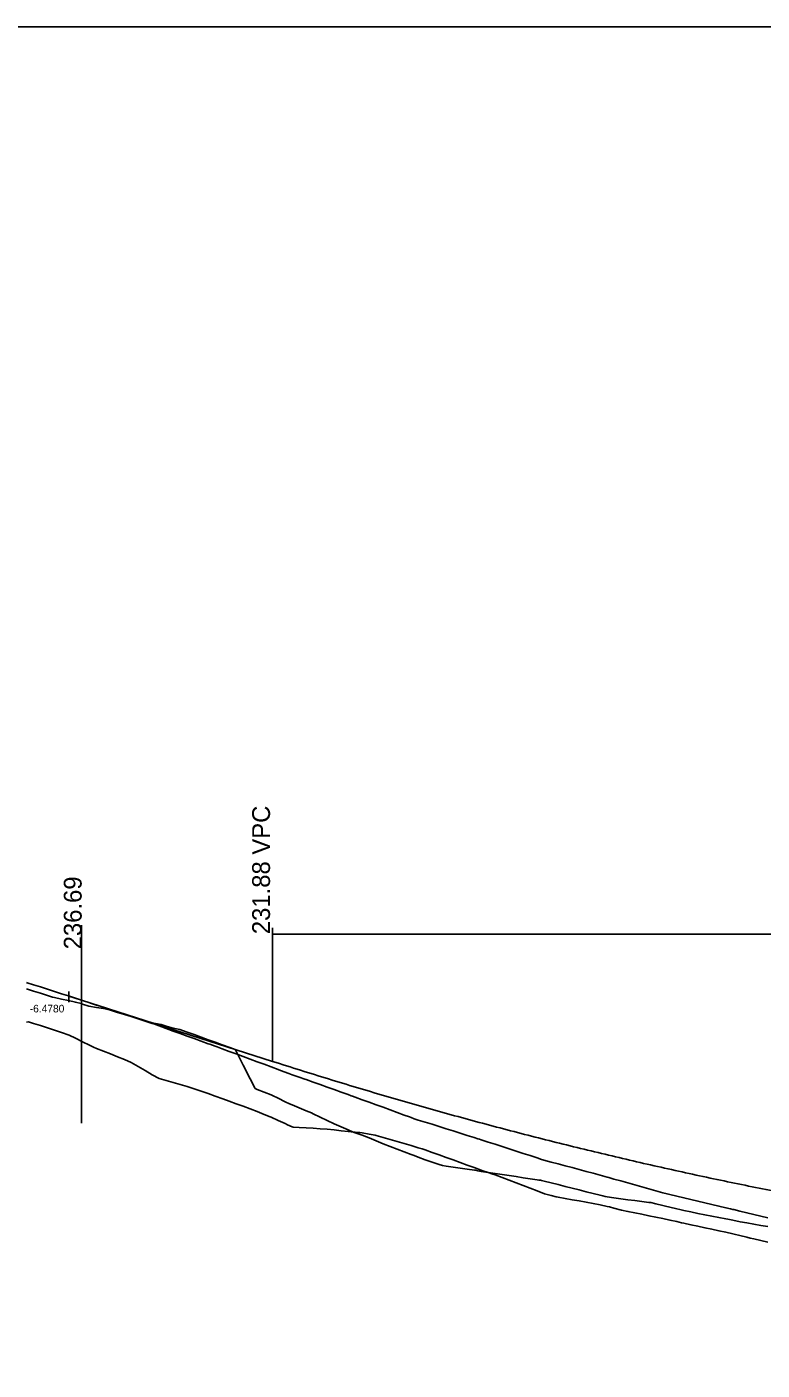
# Model space of a CAD drawing. Extents: x 2224795 to 2228395, y 930927 to 933127.
# Drawn here: x 2225784 to 2226072, y 932027 to 932554 of the extents above; entities that cross this region are included whole.
import ezdxf

# ---------------------------------------------------------------- set-up
doc = ezdxf.new("R2010")
doc.units = 0
for name, color, linetype in [('BR_EXIST_GROUND_LT', 7, 'Continuous'), ('BR_EXIST_GROUND_RT', 7, 'Continuous'), ('BR_USER NOTES', 7, 'Continuous'), ('RD_DDB_Profile_EX', 7, 'Continuous'), ('RD_DDB_Profile_Lbl', 7, 'Continuous'), ('RD_DDB_Profile_PR', 7, 'Continuous'), ('RD_DDB_StripGrade', 7, 'Continuous'), ('RD_DDB_VCLbl', 7, 'Continuous'), ('RD_SHT_ShtClip', 7, 'Continuous')]:
    doc.layers.add(name, color=color, linetype=linetype)

msp = doc.modelspace()

# ---------------------------------------------------------------- linework, layer by layer
at = {"layer": 'BR_EXIST_GROUND_LT'}
msp.add_lwpolyline([(2225783.36, 932163.35), (2225784.22, 932163.44), (2225786.11, 932162.85), (2225788.86, 932161.98), (2225791.6, 932161.1), (2225794.35, 932160.19), (2225797.1, 932159.27), (2225800.1, 932158.24), (2225802.6, 932157.01), (2225805.35, 932155.65), (2225808.09, 932154.26), (2225809.67, 932153.45), (2225810.84, 932153), (2225813.59, 932151.94), (2225816.34, 932150.85), (2225819.09, 932149.73), (2225821.84, 932148.6), (2225824.58, 932147.42), (2225827.33, 932145.87), (2225830.08, 932144.29), (2225832.83, 932142.69), (2225835.58, 932141.15), (2225838.33, 932140.41), (2225841.07, 932139.63), (2225843.82, 932138.83), (2225846.57, 932138.01), (2225849.32, 932137.16), (2225852.07, 932136.28), (2225854.81, 932135.3), (2225857.56, 932134.29), (2225860.57, 932133.16), (2225863.06, 932132.29), (2225865.81, 932131.3), (2225868.56, 932130.29), (2225871.3, 932129.25), (2225874.05, 932128.18), (2225876.8, 932127.09), (2225879.15, 932126.14), (2225879.55, 932125.96), (2225882.3, 932124.73), (2225885.05, 932123.46), (2225885.91, 932123.06), (2225887.79, 932122.24), (2225888.15, 932122.07), (2225890.54, 932121.97), (2225893.29, 932121.82), (2225896.04, 932121.65), (2225898.79, 932121.45), (2225901.54, 932121.23), (2225904.28, 932120.98), (2225907.03, 932120.7), (2225909.78, 932120.39), (2225911.98, 932120.13), (2225912.53, 932120.09), (2225913.43, 932120.01), (2225914.33, 932119.94), (2225915.28, 932119.79), (2225918.03, 932119.36), (2225920.41, 932118.97), (2225920.77, 932118.86), (2225923.52, 932118.07), (2225926.27, 932117.26), (2225929.02, 932116.46), (2225931.77, 932115.64), (2225934.51, 932114.83), (2225937.26, 932114), (2225938.86, 932113.51), (2225940.01, 932113.11), (2225942.76, 932112.14), (2225945.51, 932111.16), (2225948.26, 932110.18), (2225951, 932109.19), (2225953.75, 932108.19), (2225956.5, 932107.19), (2225959.25, 932106.18), (2225962, 932105.16), (2225962.34, 932105.04), (2225964.75, 932104.26), (2225966.26, 932103.76), (2225967.49, 932103.3), (2225970.24, 932102.27), (2225972.99, 932101.24), (2225975.74, 932100.19), (2225978.49, 932099.14), (2225981.24, 932098.08), (2225983.98, 932097.02), (2225986.92, 932095.87), (2225989.48, 932095.23), (2225991.55, 932094.71), (2225992.23, 932094.59), (2225994.98, 932094.09), (2225997.73, 932093.59), (2226000.47, 932093.08), (2226003.22, 932092.56), (2226005.97, 932092.04), (2226008.72, 932091.51), (2226011.47, 932090.98), (2226012.4, 932090.8), (2226014.21, 932090.3), (2226017.15, 932089.5), (2226019.71, 932088.99), (2226022.46, 932088.43), (2226025.21, 932087.87), (2226027.96, 932087.31), (2226030.7, 932086.74), (2226033.45, 932086.17), (2226036.2, 932085.59), (2226038.95, 932084.96), (2226040.74, 932084.54), (2226041.7, 932084.34), (2226044.45, 932083.76), (2226047.19, 932083.17), (2226049.94, 932082.58), (2226052.69, 932081.98), (2226055.44, 932081.38), (2226058.19, 932080.77), (2226060.94, 932080.16), (2226061.39, 932080.06), (2226063.68, 932079.5), (2226066.43, 932078.82), (2226067.77, 932078.49), (2226069.18, 932078.17), (2226071.93, 932077.54), (2226074.68, 932076.9)], dxfattribs=at)
at = {"layer": 'BR_EXIST_GROUND_RT'}
msp.add_lwpolyline([(2225783.36, 932176.39), (2225786.11, 932175.53), (2225788.86, 932174.68), (2225791.6, 932173.82), (2225793.61, 932173.21), (2225794.35, 932173.04), (2225797.1, 932172.41), (2225799.85, 932171.78), (2225802.6, 932171.14), (2225804.82, 932170.63), (2225805.35, 932170.45), (2225807.86, 932169.61), (2225810.84, 932169.14), (2225813.59, 932168.7), (2225814.29, 932168.59), (2225816.34, 932167.98), (2225819.09, 932167.16), (2225821.84, 932166.33), (2225824.58, 932165.51), (2225827.33, 932164.69), (2225830.08, 932163.87), (2225832.38, 932163.18), (2225832.83, 932163.09), (2225835.58, 932162.51), (2225836.32, 932162.35), (2225838.33, 932161.79), (2225841.07, 932161.02), (2225841.7, 932160.84), (2225843.59, 932160.5), (2225846.57, 932159.42), (2225849.32, 932158.42), (2225852.07, 932157.42), (2225854.81, 932156.43), (2225857.56, 932155.43), (2225860.31, 932154.43), (2225863.34, 932153.33), (2225865.41, 932152.64), (2225865.81, 932151.87), (2225868.56, 932146.47), (2225871.3, 932141.08), (2225873.25, 932137.27), (2225874.05, 932136.94), (2225876.8, 932135.83), (2225879.55, 932134.75), (2225880.07, 932134.54), (2225882.3, 932133.43), (2225885.05, 932132.07), (2225886.67, 932131.28), (2225887.79, 932130.8), (2225890.54, 932129.64), (2225893.29, 932128.5), (2225895.36, 932127.66), (2225896.04, 932127.33), (2225898.79, 932126.01), (2225901.54, 932124.72), (2225904.28, 932123.45), (2225907.03, 932122.2), (2225909.78, 932120.98), (2225911.48, 932120.24), (2225912.53, 932119.86), (2225915.28, 932118.9), (2225917.02, 932118.31), (2225918.03, 932117.88), (2225920.77, 932116.71), (2225923.52, 932115.58), (2225926.27, 932114.47), (2225929.02, 932113.39), (2225931.77, 932112.33), (2225934.51, 932111.3), (2225935.66, 932110.9), (2225937.26, 932110.3), (2225940.01, 932109.31), (2225942.76, 932108.35), (2225945.51, 932107.41), (2225946.79, 932106.99), (2225948.26, 932106.78), (2225951, 932106.38), (2225953.75, 932105.99), (2225956.5, 932105.6), (2225959.44, 932105.18), (2225959.87, 932105.24), (2225960.73, 932104.88), (2225962, 932104.69), (2225964.75, 932104.28), (2225967.49, 932103.87), (2225970.24, 932103.46), (2225972.99, 932103.05), (2225975.74, 932102.64), (2225978.49, 932102.23), (2225981.24, 932101.83), (2225983.98, 932101.42), (2225984.67, 932101.32), (2225985.37, 932101.22), (2225985.69, 932101.19), (2225986.73, 932100.92), (2225989.48, 932100.22), (2225992.23, 932099.52), (2225994.98, 932098.83), (2225997.73, 932098.13), (2226000.47, 932097.44), (2226003.22, 932096.74), (2226005.97, 932096.05), (2226008.72, 932095.35), (2226009.76, 932095.09), (2226010.71, 932094.85), (2226011.47, 932094.74), (2226014.21, 932094.34), (2226016.96, 932093.95), (2226019.71, 932093.58), (2226022.46, 932093.23), (2226025.21, 932092.88), (2226027.96, 932092.55), (2226028.69, 932092.46), (2226030.7, 932091.94), (2226033.45, 932091.25), (2226034.44, 932091.02), (2226036.2, 932090.6), (2226038.95, 932089.95), (2226040.08, 932089.69), (2226041.7, 932089.35), (2226044.45, 932088.78), (2226047.19, 932088.22), (2226049.94, 932087.66), (2226052.69, 932087.12), (2226055.44, 932086.59), (2226058.19, 932086.06), (2226058.91, 932085.93), (2226060.94, 932085.5), (2226063.77, 932084.92), (2226066.43, 932084.44), (2226069.18, 932083.95), (2226071.93, 932083.47), (2226074.68, 932083)], dxfattribs=at)
at = {"layer": 'BR_USER NOTES'}
for p, q in [((2225805.06, 932201.39), (2225805.06, 932123.59)), ((2225800.06, 932175.38), (2225800.06, 932171.18)), ((2225805.06, 932171.94), (2225800.06, 932173.56))]:
    msp.add_line(p, q, dxfattribs=at)
at = {"layer": 'RD_DDB_Profile_EX'}
msp.add_lwpolyline([(2225783.36, 932178.93), (2225783.67, 932178.83), (2225786.11, 932178.05), (2225788.86, 932177.17), (2225791.6, 932176.29), (2225794.35, 932175.4), (2225797.1, 932174.52), (2225799.85, 932173.63), (2225802.6, 932172.74), (2225805.35, 932171.85), (2225808.23, 932170.91), (2225808.59, 932170.78), (2225810.84, 932170.05), (2225813.59, 932169.16), (2225816.34, 932168.26), (2225819.09, 932167.36), (2225821.84, 932166.45), (2225824.58, 932165.55), (2225827.33, 932164.64), (2225830.08, 932163.73), (2225832.33, 932162.99), (2225832.83, 932162.81), (2225833.38, 932162.62), (2225835.58, 932161.83), (2225838.33, 932160.84), (2225841.07, 932159.85), (2225843.82, 932158.86), (2225846.57, 932157.86), (2225849.32, 932156.87), (2225852.07, 932155.87), (2225854.81, 932154.87), (2225855.46, 932154.63), (2225857.56, 932153.86), (2225858.29, 932153.6), (2225860.31, 932152.86), (2225863.06, 932151.85), (2225865.81, 932150.84), (2225868.56, 932149.82), (2225871.3, 932148.81), (2225874.05, 932147.79), (2225875.59, 932147.22), (2225876.8, 932146.77), (2225879.55, 932145.75), (2225882.3, 932144.72), (2225883.24, 932144.35), (2225885.05, 932143.67), (2225886.03, 932143.3), (2225886.4, 932143.18), (2225887.79, 932142.69), (2225890.54, 932141.72), (2225892.7, 932140.97), (2225893.29, 932140.76), (2225896.04, 932139.78), (2225898.79, 932138.8), (2225901.54, 932137.82), (2225904.28, 932136.84), (2225907.03, 932135.85), (2225909.78, 932134.86), (2225910.95, 932134.44), (2225911.48, 932134.25), (2225912.53, 932133.88), (2225915.28, 932132.88), (2225918.03, 932131.88), (2225920.77, 932130.88), (2225923.52, 932129.88), (2225926.27, 932128.87), (2225929.02, 932127.86), (2225931.77, 932126.85), (2225933.81, 932126.1), (2225934.51, 932125.84), (2225935.72, 932125.39), (2225937.33, 932124.89), (2225940.01, 932124.06), (2225942.76, 932123.2), (2225945.51, 932122.34), (2225948.26, 932121.47), (2225951, 932120.61), (2225953.75, 932119.74), (2225956.5, 932118.86), (2225959.25, 932117.99), (2225960.65, 932117.54), (2225961.38, 932117.31), (2225962, 932117.11), (2225964.75, 932116.23), (2225967.49, 932115.34), (2225970.24, 932114.46), (2225972.99, 932113.57), (2225975.74, 932112.68), (2225978.49, 932111.78), (2225981.24, 932110.89), (2225983.98, 932109.99), (2225985.79, 932109.39), (2225986.27, 932109.24), (2225986.64, 932109.14), (2225989.48, 932108.38), (2225992.23, 932107.65), (2225994.98, 932106.91), (2225997.73, 932106.18), (2226000.47, 932105.44), (2226003.22, 932104.69), (2226005.97, 932103.95), (2226008.72, 932103.2), (2226011.47, 932102.45), (2226012.2, 932102.25), (2226014.21, 932101.7), (2226016.96, 932100.94), (2226019.71, 932100.18), (2226022.46, 932099.42), (2226025.21, 932098.65), (2226027.96, 932097.88), (2226030.7, 932097.11), (2226033.45, 932096.34), (2226035.07, 932095.88), (2226035.65, 932095.75), (2226036.2, 932095.62), (2226038.95, 932094.98), (2226041.7, 932094.34), (2226044.45, 932093.69), (2226047.19, 932093.05), (2226049.94, 932092.39), (2226052.69, 932091.74), (2226055.44, 932091.09), (2226058.19, 932090.43), (2226060.01, 932089.99), (2226060.94, 932089.77), (2226061.29, 932089.68), (2226063.68, 932089.1), (2226066.43, 932088.44), (2226069.18, 932087.77), (2226071.93, 932087.09), (2226074.68, 932086.42)], dxfattribs=at)
at = {"layer": 'RD_DDB_Profile_PR'}
msp.add_line((2225805.06, 932171.94), (2225880.06, 932147.9), dxfattribs=at)
msp.add_spline([(2225880.06, 932147.9), (2225891.06, 932144.42), (2225902.06, 932141.01), (2225913.06, 932137.67), (2225924.06, 932134.41), (2225935.06, 932131.23), (2225946.06, 932128.12), (2225957.06, 932125.09), (2225968.06, 932122.14), (2225979.06, 932119.26), (2225990.06, 932116.45), (2226001.06, 932113.73), (2226012.06, 932111.08), (2226023.06, 932108.5), (2226034.06, 932106), (2226045.06, 932103.58), (2226056.06, 932101.23), (2226067.06, 932098.96), (2226078.06, 932096.77), (2226089.06, 932094.65), (2226100.06, 932092.6), (2226111.06, 932090.64), (2226122.06, 932088.75), (2226133.06, 932086.93), (2226144.06, 932085.19), (2226155.06, 932083.53), (2226166.06, 932081.94), (2226177.06, 932080.43), (2226188.06, 932079), (2226199.06, 932077.64), (2226210.06, 932076.35), (2226221.06, 932075.15), (2226232.06, 932074.02), (2226243.06, 932072.96), (2226254.06, 932071.98), (2226265.06, 932071.08), (2226276.06, 932070.25), (2226287.06, 932069.5), (2226298.06, 932068.83), (2226309.06, 932068.23), (2226320.06, 932067.7), (2226331.06, 932067.26), (2226342.06, 932066.89), (2226353.06, 932066.59), (2226364.06, 932066.37), (2226375.06, 932066.23), (2226386.06, 932066.16), (2226397.06, 932066.17), (2226408.06, 932066.26), (2226419.06, 932066.42), (2226430.06, 932066.65)], degree=3, dxfattribs=at)
at = {"layer": 'RD_DDB_VCLbl'}
for p, q in [((2225880.06, 932200.4), (2225880.06, 932147.9)), ((2225880.06, 932197.9), (2226430.06, 932197.9))]:
    msp.add_line(p, q, dxfattribs=at)
at = {"layer": 'RD_SHT_ShtClip'}
msp.add_lwpolyline([(2225474.62, 932554.3), (2227274.62, 932554.3), (2227274.62, 931454.3), (2225474.62, 931454.3)], close=True, dxfattribs=at)

# ---------------------------------------------------------------- texts
at = {"layer": 'BR_USER NOTES'}
msp.add_text('-6.4780', height=3, dxfattribs=at).set_placement((2225784.66, 932167.15))
at = {"layer": 'RD_DDB_Profile_Lbl'}
msp.add_text('236.69', height=7, rotation=90, dxfattribs=at).set_placement((2225805.06, 932191.94))
at = {"layer": 'RD_DDB_StripGrade'}
msp.add_text('231.88 VPC', height=7, rotation=90, dxfattribs=at).set_placement((2225879.06, 932197.9))

doc.saveas('drawing.dxf')
